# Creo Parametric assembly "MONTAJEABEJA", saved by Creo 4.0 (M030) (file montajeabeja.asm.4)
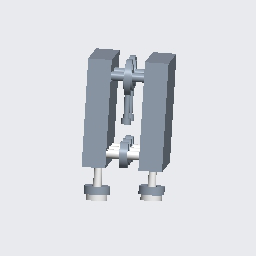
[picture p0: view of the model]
Units: millimeter Newton Second (mmNs); MM, TONNE, SECS

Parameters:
  MODELED_BY = "aj"

Created from: MMNS_ASM_DESIGN.ASM

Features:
  1. datum plane "ASM_RIGHT"
  2. datum plane "ASM_TOP"
  3. datum plane "ASM_FRONT"
  4. coordinate system
  5. component "LADOSUNIONESABEJA"
  6. component "EJECENTROABEJA"
  7. component "EJECENTROABEJA"
  8. component "EJECENTROABEJA"
  9. component "LADOSUNIONESABEJA"
  10. component "EJELATERALABEJA"
  11. component "EJELATERALABEJA"
  12. component "EJERUEDASCENTROABEJA"
  13. component "RODAMIENTOABEJA"
  14. component "SOPORTEPESO"
  15. component "EJERUEDASCENTROABEJA"
  16. component "RODAMIENTOABEJA"
  17. component "SOPORTEPESO"

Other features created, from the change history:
  component "LADOSUNIONESABEJA.PRT"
